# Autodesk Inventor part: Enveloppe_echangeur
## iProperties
Shininess: 64.0
Length Units: 11269
Angle Units: 11279
Time Units: 11290
Mass Units: 11283
Length Display Precision: 3
Angle Display Precision: 2
Compacted: True
Part Number: Enveloppe_echangeur
Document SubType Name: Modeling
Created: 2008-02
Material: Acier inoxydable, austénitique
Designer: Pascal
Density: 8.03 g/cm^3
Density: 0.0
Volumn: 0.0
Area: 0.0
PropertySet Name: Model Information
Control State: 0
Master: False
Checked Out: False
MATIERE_PIECE: X2CrNi 18-11
OBSERVATIONS: Øext 698,5 ep 3,17
DESIGNATION: Enveloppe echangeur
Author: Pascal
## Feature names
1. Extrusion1
2. Extrusion2
3. Extrusion3
4. Extrusion4
5. Extrusion5
6. Extrusion6
7. Extrusion7
8. Extrusion8
9. Extrusion9
